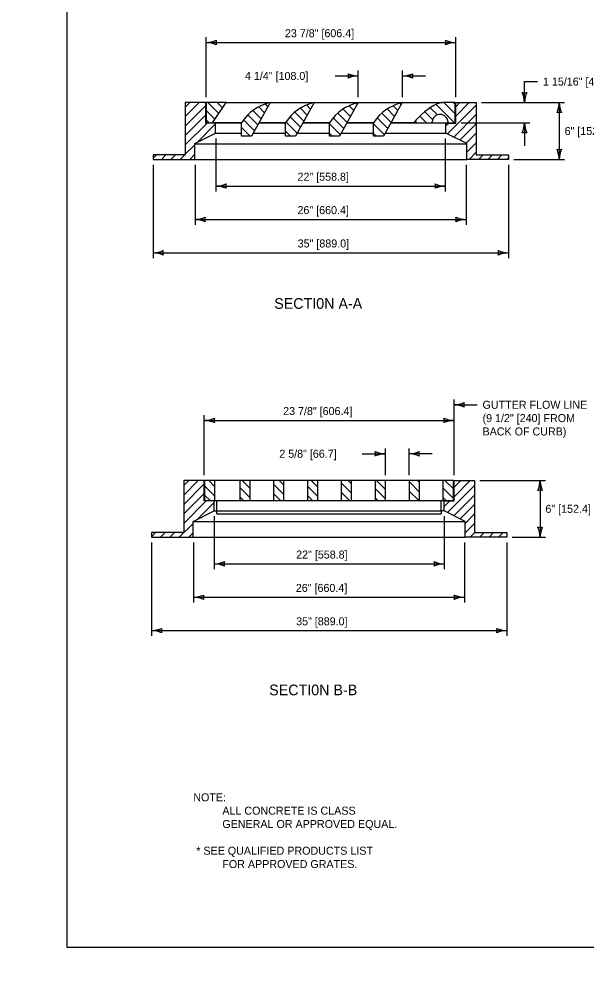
# Model space of a CAD drawing. Extents: x 49991.4 to 50021, y 49987.6 to 50011.4.
# Drawn here: x 49999.98 to 50004.23, y 49999.86 to 50007.02 of the extents above; entities that cross this region are included whole.
import ezdxf

# ---------------------------------------------------------------- set-up
doc = ezdxf.new("R2010")
doc.units = 0
for name, color, linetype in [('Level 1', 7, 'Continuous'), ('Level 2', 7, 'Continuous'), ('Level 3', 7, 'Continuous'), ('Level 4', 7, 'Continuous')]:
    doc.layers.add(name, color=color, linetype=linetype)

msp = doc.modelspace()

# ---------------------------------------------------------------- linework, layer by layer
at = {"layer": 'Level 1'}
for p, q in [((50001.3764, 50006.3907), (50001.2224, 50006.3907)), ((50001.2224, 50006.3907), (50001.2224, 50006)), ((50001.2224, 50006.3569), (50001.2562, 50006.3907)), ((50001.2224, 50006.2862), (50001.3269, 50006.3907)), ((50001.2224, 50006.2155), (50001.3764, 50006.3695)), ((50001.3764, 50006.237), (50001.3764, 50006.3907)), ((50001.5288, 50006.3907), (50001.3786, 50006.3907)), ((50001.3786, 50006.3907), (50001.3786, 50006.2393)), ((50001.4729, 50006.309), (50001.3912, 50006.3907)), ((50001.4251, 50006.2393), (50001.5288, 50006.3907)), ((50001.5016, 50006.351), (50001.4619, 50006.3907)), ((50001.5288, 50006.3907), (50003.1532, 50006.3907)), ((50001.8588, 50006.3907), (50001.7185, 50006.1398)), ((50001.8166, 50006.3153), (50001.7724, 50006.3596)), ((50001.842, 50006.3606), (50001.8222, 50006.3804)), ((50002.1888, 50006.3907), (50002.0485, 50006.1398)), ((50002.1618, 50006.3425), (50002.1314, 50006.3729)), ((50002.1872, 50006.3878), (50002.1852, 50006.3899)), ((50002.5188, 50006.3907), (50002.3785, 50006.1398)), ((50002.4859, 50006.3318), (50002.4499, 50006.3678)), ((50002.5112, 50006.3772), (50002.5018, 50006.3866)), ((50002.8488, 50006.3907), (50002.7085, 50006.1398)), ((50002.8159, 50006.3318), (50002.7799, 50006.3678)), ((50002.8412, 50006.3771), (50002.8317, 50006.3866)), ((50003.241, 50006.2393), (50003.1031, 50006.3772)), ((50003.2438, 50006.3907), (50003.1532, 50006.3907)), ((50003.2438, 50006.3072), (50003.1603, 50006.3907)), ((50003.1866, 50006.1565), (50003.4028, 50006.3727)), ((50003.2438, 50006.3779), (50003.231, 50006.3907)), ((50003.2438, 50006.2393), (50003.2438, 50006.3907)), ((50003.2438, 50006.2393), (50003.2438, 50006.3907)), ((50003.2488, 50006.237), (50003.2488, 50006.3907)), ((50003.2488, 50006.3907), (50003.4028, 50006.3907)), ((50003.2488, 50006.3602), (50003.2793, 50006.3907)), ((50003.2488, 50006.2894), (50003.3501, 50006.3907)), ((50003.4028, 50006.3907), (50003.4028, 50006)), ((50001.2224, 50006.1448), (50001.3764, 50006.2988)), ((50001.4441, 50006.2671), (50001.3786, 50006.3326)), ((50001.5003, 50006.3491), (50001.5003, 50006.3491)), ((50001.5003, 50006.3491), (50001.5003, 50006.3491)), ((50001.7659, 50006.2246), (50001.6912, 50006.2994)), ((50001.7913, 50006.2699), (50001.7292, 50006.332)), ((50002.1111, 50006.2518), (50002.0431, 50006.3198)), ((50002.1365, 50006.2971), (50002.0845, 50006.3491)), ((50002.4351, 50006.2411), (50002.3645, 50006.3117)), ((50002.4605, 50006.2864), (50002.404, 50006.343)), ((50002.7651, 50006.2411), (50002.6945, 50006.3117)), ((50002.7905, 50006.2864), (50002.734, 50006.343)), ((50003.0289, 50006.2393), (50002.9793, 50006.2888)), ((50003.0756, 50006.2632), (50003.0168, 50006.322)), ((50003.1116, 50006.298), (50003.058, 50006.3516)), ((50003.2337, 50006.133), (50003.4028, 50006.302)), ((50001.2224, 50006.0741), (50001.3853, 50006.237)), ((50001.3126, 50006.0936), (50001.4496, 50006.2306)), ((50001.4496, 50006.237), (50001.3764, 50006.237)), ((50001.4012, 50006.2393), (50001.3786, 50006.2619)), ((50001.3786, 50006.2393), (50001.4251, 50006.2393)), ((50001.644, 50006.2393), (50001.4251, 50006.2393)), ((50001.4428, 50006.2652), (50001.4428, 50006.2652)), ((50001.4428, 50006.2652), (50001.4428, 50006.2652)), ((50001.4496, 50006.162), (50001.4496, 50006.237)), ((50001.644, 50006.237), (50001.4496, 50006.237)), ((50001.644, 50006.1398), (50001.644, 50006.2393)), ((50001.7406, 50006.1792), (50001.6589, 50006.2609)), ((50001.974, 50006.237), (50001.7729, 50006.237)), ((50001.974, 50006.2393), (50001.7741, 50006.2393)), ((50001.974, 50006.1398), (50001.974, 50006.2393)), ((50002.0604, 50006.1611), (50001.9773, 50006.2441)), ((50002.0858, 50006.2064), (50002.0077, 50006.2845)), ((50002.304, 50006.237), (50002.1029, 50006.237)), ((50002.304, 50006.2393), (50002.1041, 50006.2393)), ((50002.304, 50006.1398), (50002.304, 50006.2393)), ((50002.3844, 50006.1504), (50002.304, 50006.2308)), ((50002.4098, 50006.1957), (50002.33, 50006.2755)), ((50002.634, 50006.237), (50002.4329, 50006.237)), ((50002.634, 50006.2393), (50002.4341, 50006.2393)), ((50002.634, 50006.1398), (50002.634, 50006.2393)), ((50002.7144, 50006.1504), (50002.634, 50006.2308)), ((50002.7398, 50006.1957), (50002.66, 50006.2755)), ((50003.1756, 50006.237), (50002.7629, 50006.237)), ((50002.9349, 50006.2393), (50002.7641, 50006.2393)), ((50002.9349, 50006.2393), (50003.0669, 50006.2393)), ((50002.9582, 50006.2393), (50002.9454, 50006.252)), ((50003.0669, 50006.2393), (50003.0672, 50006.2394)), ((50003.0669, 50006.2393), (50003.1966, 50006.2393)), ((50003.1756, 50006.162), (50003.1756, 50006.237)), ((50003.1756, 50006.237), (50003.2488, 50006.237)), ((50003.1756, 50006.2162), (50003.1964, 50006.237)), ((50003.1967, 50006.2393), (50003.2438, 50006.2393)), ((50003.2809, 50006.1094), (50003.4028, 50006.2313)), ((50001.2934, 50006.084), (50001.4496, 50006.162)), ((50001.4496, 50006.1607), (50001.644, 50006.1607)), ((50001.7093, 50006.1398), (50001.644, 50006.2051)), ((50001.7302, 50006.1607), (50001.974, 50006.1607)), ((50002.0109, 50006.1398), (50001.974, 50006.1767)), ((50002.0602, 50006.1607), (50002.304, 50006.1607)), ((50002.3243, 50006.1398), (50002.304, 50006.1601)), ((50002.3902, 50006.1607), (50002.634, 50006.1607)), ((50002.6543, 50006.1398), (50002.634, 50006.1601)), ((50002.7202, 50006.1607), (50003.1756, 50006.1607)), ((50003.3318, 50006.084), (50003.1756, 50006.162)), ((50003.3281, 50006.0859), (50003.4028, 50006.1606)), ((50001.2224, 50006.0034), (50001.2934, 50006.0744)), ((50001.2934, 50005.9654), (50001.2934, 50006.084)), ((50001.2934, 50006.0826), (50003.3318, 50006.0826)), ((50001.7185, 50006.1398), (50001.644, 50006.1398)), ((50002.0485, 50006.1398), (50001.974, 50006.1398)), ((50002.3785, 50006.1398), (50002.304, 50006.1398)), ((50002.7085, 50006.1398), (50002.634, 50006.1398)), ((50003.3318, 50006.0189), (50003.4028, 50006.0899)), ((50003.3318, 50005.9654), (50003.3318, 50006.084)), ((50001.2224, 50006), (50000.981, 50006)), ((50000.981, 50006), (50000.981, 50005.9654)), ((50000.981, 50005.9741), (50001.0069, 50006)), ((50001.043, 50005.9654), (50001.0776, 50006)), ((50001.1137, 50005.9654), (50001.1483, 50006)), ((50001.1844, 50005.9654), (50001.219, 50006)), ((50001.2551, 50005.9654), (50001.2934, 50006.0037)), ((50003.349, 50005.9654), (50003.4028, 50006.0192)), ((50003.4028, 50006), (50003.6442, 50006)), ((50003.4197, 50005.9654), (50003.4543, 50006)), ((50003.4904, 50005.9654), (50003.525, 50006)), ((50003.5612, 50005.9654), (50003.5958, 50006)), ((50003.6442, 50006), (50003.6442, 50005.9654)), ((50000.981, 50005.9654), (50001.2934, 50005.9654)), ((50001.2934, 50005.9654), (50003.3318, 50005.9654)), ((50003.6442, 50005.9654), (50003.3318, 50005.9654)), ((50003.6319, 50005.9654), (50003.6442, 50005.9777)), ((50001.3642, 50003.5597), (50001.2102, 50003.5597)), ((50001.2102, 50003.5597), (50001.2102, 50003.1691)), ((50001.2102, 50003.5207), (50001.2492, 50003.5597)), ((50001.2102, 50003.45), (50001.3199, 50003.5597)), ((50001.2102, 50003.3793), (50001.3642, 50003.5333)), ((50001.3642, 50003.406), (50001.3642, 50003.5597)), ((50001.3664, 50003.5597), (50001.3664, 50003.4083)), ((50001.3664, 50003.5597), (50001.3664, 50003.4083)), ((50003.2316, 50003.5597), (50001.3664, 50003.5597)), ((50001.3664, 50003.5597), (50001.3664, 50003.5594)), ((50001.3664, 50003.5597), (50001.3664, 50003.4083)), ((50001.4446, 50003.5597), (50001.3664, 50003.5597)), ((50001.4446, 50003.4422), (50001.3664, 50003.5204)), ((50001.4446, 50003.5129), (50001.3978, 50003.5597)), ((50001.4446, 50003.4083), (50001.4446, 50003.5597)), ((50001.63, 50003.5597), (50001.63, 50003.4083)), ((50001.7082, 50003.5597), (50001.63, 50003.5597)), ((50001.7082, 50003.4297), (50001.63, 50003.5079)), ((50001.7082, 50003.5004), (50001.6489, 50003.5597)), ((50001.7082, 50003.4083), (50001.7082, 50003.5597)), ((50001.8836, 50003.5597), (50001.8836, 50003.4083)), ((50001.9618, 50003.5597), (50001.8836, 50003.5597)), ((50001.9618, 50003.4534), (50001.8836, 50003.5316)), ((50001.9618, 50003.5241), (50001.9262, 50003.5597)), ((50001.9618, 50003.4083), (50001.9618, 50003.5597)), ((50002.1372, 50003.5597), (50002.1372, 50003.4083)), ((50002.2152, 50003.5597), (50002.1372, 50003.5597)), ((50002.2152, 50003.4386), (50002.1372, 50003.5166)), ((50002.2152, 50003.5093), (50002.1648, 50003.5597)), ((50002.2152, 50003.4083), (50002.2152, 50003.5597)), ((50002.3906, 50003.5597), (50002.3906, 50003.4083)), ((50002.4688, 50003.5597), (50002.3906, 50003.5597)), ((50002.4688, 50003.4635), (50002.3906, 50003.5417)), ((50002.4688, 50003.5342), (50002.4433, 50003.5597)), ((50002.4688, 50003.4083), (50002.4688, 50003.5597)), ((50002.6442, 50003.5597), (50002.6442, 50003.4083)), ((50002.7222, 50003.5597), (50002.6442, 50003.5597)), ((50002.7222, 50003.4214), (50002.6442, 50003.4994)), ((50002.7222, 50003.4921), (50002.6546, 50003.5597)), ((50002.7222, 50003.4083), (50002.7222, 50003.5597)), ((50002.8996, 50003.5597), (50002.8996, 50003.4083)), ((50002.9778, 50003.5597), (50002.8996, 50003.5597)), ((50002.9778, 50003.4728), (50002.8996, 50003.551)), ((50002.9778, 50003.5435), (50002.9616, 50003.5597)), ((50002.9778, 50003.4083), (50002.9778, 50003.5597)), ((50003.1536, 50003.5597), (50003.1536, 50003.4083)), ((50003.2316, 50003.5597), (50003.1536, 50003.5597)), ((50003.2316, 50003.4256), (50003.1536, 50003.5036)), ((50003.2316, 50003.4963), (50003.1682, 50003.5597)), ((50003.1881, 50003.3187), (50003.3906, 50003.5212)), ((50003.2316, 50003.4083), (50003.2316, 50003.5597)), ((50003.2366, 50003.406), (50003.2366, 50003.5597)), ((50003.2366, 50003.5597), (50003.3906, 50003.5597)), ((50003.2366, 50003.5087), (50003.2876, 50003.5597)), ((50003.2366, 50003.438), (50003.3583, 50003.5597)), ((50003.3906, 50003.5597), (50003.3906, 50003.1691)), ((50003.3906, 50003.5597), (50003.3906, 50003.1691)), ((50001.2102, 50003.3086), (50001.3642, 50003.4626)), ((50001.4078, 50003.4083), (50001.3664, 50003.4497)), ((50001.6589, 50003.4083), (50001.63, 50003.4372)), ((50001.9362, 50003.4083), (50001.8836, 50003.4609)), ((50002.1748, 50003.4083), (50002.1372, 50003.4459)), ((50002.4532, 50003.4083), (50002.3906, 50003.4709)), ((50002.6646, 50003.4083), (50002.6442, 50003.4287)), ((50002.9716, 50003.4083), (50002.8996, 50003.4803)), ((50003.1782, 50003.4083), (50003.1536, 50003.4329)), ((50003.2352, 50003.2952), (50003.3906, 50003.4505)), ((50001.2102, 50003.2379), (50001.3783, 50003.406)), ((50001.3109, 50003.2679), (50001.4374, 50003.3943)), ((50001.4374, 50003.406), (50001.3642, 50003.406)), ((50001.3664, 50003.4083), (50001.4446, 50003.4083)), ((50001.4374, 50003.3311), (50001.4374, 50003.406)), ((50001.4446, 50003.4083), (50001.4592, 50003.4083)), ((50001.4592, 50003.3091), (50001.4592, 50003.4083)), ((50001.63, 50003.4083), (50001.7082, 50003.4083)), ((50001.8836, 50003.4083), (50001.9618, 50003.4083)), ((50002.1372, 50003.4083), (50002.2152, 50003.4083)), ((50002.3906, 50003.4083), (50002.4688, 50003.4083)), ((50002.6442, 50003.4083), (50002.7222, 50003.4083)), ((50002.9009, 50003.4083), (50002.8996, 50003.4096)), ((50002.8996, 50003.4083), (50002.9778, 50003.4083)), ((50003.1388, 50003.3297), (50003.1388, 50003.4083)), ((50003.1388, 50003.4083), (50003.1536, 50003.4083)), ((50003.1536, 50003.4083), (50003.2316, 50003.4083)), ((50003.1634, 50003.3311), (50003.1634, 50003.406)), ((50003.1634, 50003.406), (50003.2366, 50003.406)), ((50003.1634, 50003.3648), (50003.2046, 50003.406)), ((50003.173, 50003.4083), (50003.2312, 50003.4083)), ((50003.2824, 50003.2716), (50003.3906, 50003.3798)), ((50001.2812, 50003.253), (50001.4374, 50003.3311)), ((50001.4374, 50003.3311), (50001.4592, 50003.3311)), ((50001.4592, 50003.3091), (50003.1388, 50003.3091)), ((50003.1634, 50003.3311), (50003.1388, 50003.3311)), ((50003.1388, 50003.3297), (50003.1388, 50003.3091)), ((50003.3196, 50003.253), (50003.1634, 50003.3311)), ((50003.3196, 50003.2381), (50003.3906, 50003.3091)), ((50001.1775, 50003.1344), (50001.2812, 50003.2381)), ((50001.2812, 50003.1344), (50001.2812, 50003.253)), ((50001.2812, 50003.2516), (50003.3196, 50003.2516)), ((50003.3196, 50003.1344), (50003.3196, 50003.253)), ((50003.3196, 50003.1674), (50003.3906, 50003.2384)), ((50001.2102, 50003.1691), (50000.9688, 50003.1691)), ((50000.9688, 50003.1691), (50000.9688, 50003.1344)), ((50000.9688, 50003.1379), (50001, 50003.1691)), ((50001.036, 50003.1344), (50001.0707, 50003.1691)), ((50001.1067, 50003.1344), (50001.1414, 50003.1691)), ((50001.2482, 50003.1344), (50001.2812, 50003.1674)), ((50003.3573, 50003.1344), (50003.392, 50003.1691)), ((50003.3906, 50003.1691), (50003.632, 50003.1691)), ((50003.428, 50003.1344), (50003.4627, 50003.1691)), ((50003.4987, 50003.1344), (50003.5334, 50003.1691)), ((50003.5694, 50003.1344), (50003.6041, 50003.1691)), ((50003.632, 50003.1691), (50003.632, 50003.1344)), ((50000.9688, 50003.1344), (50001.2812, 50003.1344)), ((50001.2834, 50003.1344), (50003.3196, 50003.1344)), ((50003.632, 50003.1344), (50003.3196, 50003.1344)), ((49999.9766, 49999.8624), (49999.9766, 49999.8624))]:
    msp.add_line(p, q, dxfattribs=at)
msp.add_lwpolyline([(50008.6146, 50011.2628), (50000.3356, 50011.2628), (50000.3356, 50000.0624), (50008.6146, 50000.0624)], close=True, dxfattribs=at)
for centre, radius, start, end in [((50001.9257, 50006.0677), 0.3298, 101.70095, 148.65461), ((50002.2557, 50006.0677), 0.3298, 101.70095, 148.65461), ((50002.5857, 50006.0677), 0.3298, 101.70095, 148.65461), ((50002.9157, 50006.0677), 0.3298, 101.70095, 148.65461), ((50003.3175, 50005.9452), 0.4825, 115.43955, 142.45364), ((50003.3175, 50005.9452), 0.4825, 115.43955, 142.45364), ((50003.1532, 50006.2907), 0.1, 90, 115.43595), ((50003.1532, 50006.2907), 0.1, 90, 115.43595), ((50003.1316, 50006.242), 0.06, 2.28125, 175.27663)]:
    msp.add_arc(centre, radius, start, end, dxfattribs=at)
for points in [[(50003.0672, 50006.2394), (50003.0681, 50006.2396), (50003.0691, 50006.2403), (50003.0702, 50006.2417), (50003.0709, 50006.2428), (50003.0715, 50006.2449), (50003.0718, 50006.2469)], [(50003.1915, 50006.2444), (50003.1916, 50006.2433), (50003.1916, 50006.2429), (50003.1917, 50006.2425), (50003.192, 50006.2416), (50003.1926, 50006.2407), (50003.1932, 50006.2404), (50003.1937, 50006.2401), (50003.1947, 50006.2397), (50003.196, 50006.2394), (50003.1967, 50006.2393)]]:
    msp.add_spline(points, degree=3, dxfattribs=at)
at = {"layer": 'Level 3'}
for p, q in [((50001.3786, 50006.4307), (50001.3786, 50006.8807)), ((50003.2488, 50006.4307), (50003.2488, 50006.8807)), ((50001.3786, 50006.8407), (50003.2488, 50006.8407)), ((50002.3454, 50006.5907), (50002.5188, 50006.5907)), ((50002.5188, 50006.4307), (50002.5188, 50006.6307)), ((50002.8502, 50006.4307), (50002.8502, 50006.6307)), ((50002.8502, 50006.5907), (50003.0236, 50006.5907)), ((50003.7644, 50006.3907), (50003.7644, 50006.5483)), ((50003.7644, 50006.5483), (50003.8629, 50006.5483)), ((50003.4428, 50006.3907), (50004.0651, 50006.3907)), ((50004.0251, 50006.3907), (50004.0251, 50005.9654)), ((50003.2888, 50006.2393), (50003.8044, 50006.2393)), ((50003.7644, 50006.2393), (50003.7644, 50006.0659)), ((50001.4518, 50006.1207), (50001.4518, 50005.7254)), ((50003.1706, 50006.1207), (50003.1706, 50005.7254)), ((50003.6842, 50005.9654), (50004.0651, 50005.9654)), ((50000.981, 50005.9254), (50000.981, 50005.2254)), ((50001.2956, 50005.9254), (50001.2956, 50005.4754)), ((50003.3268, 50005.9254), (50003.3268, 50005.4754)), ((50003.6442, 50005.9254), (50003.6442, 50005.2254)), ((50001.4518, 50005.7654), (50003.1706, 50005.7654)), ((50001.2956, 50005.5154), (50003.3268, 50005.5154)), ((50000.981, 50005.2654), (50003.6442, 50005.2654)), ((50003.2366, 50003.5997), (50003.2366, 50004.1668)), ((50003.2366, 50004.1268), (50003.41, 50004.1268)), ((50001.3642, 50003.5997), (50001.3642, 50004.0497)), ((50001.3642, 50004.0097), (50003.2366, 50004.0097)), ((50002.7222, 50003.5997), (50002.7222, 50003.7997)), ((50002.8996, 50003.5997), (50002.8996, 50003.7997)), ((50002.5488, 50003.7597), (50002.7222, 50003.7597)), ((50003.073, 50003.7597), (50002.8996, 50003.7597)), ((50003.4306, 50003.5597), (50003.9212, 50003.5597)), ((50003.8812, 50003.5597), (50003.8812, 50003.1344)), ((50001.4389, 50003.2911), (50001.4389, 50002.8944)), ((50003.1634, 50003.2911), (50003.1634, 50002.8944)), ((50000.9688, 50003.0944), (50000.9688, 50002.3944)), ((50001.2834, 50003.0944), (50001.2834, 50002.6444)), ((50003.3146, 50003.0944), (50003.3146, 50002.6444)), ((50003.632, 50003.0944), (50003.632, 50002.3944)), ((50003.672, 50003.1344), (50003.9212, 50003.1344)), ((50001.4389, 50002.9344), (50003.1634, 50002.9344)), ((50001.2834, 50002.6844), (50003.3146, 50002.6844)), ((50000.9688, 50002.4344), (50003.632, 50002.4344))]:
    msp.add_line(p, q, dxfattribs=at)
for centre, radius, start, end in [((50001.3671, 50007.0734), 0.233, 272.82731, 292.07716), ((50001.5068, 50006.8407), 0.0548, 162.13882, 197.86118), ((50003.258, 50007.0628), 0.2223, 247.45601, 267.63952), ((50003.1206, 50006.8407), 0.0548, 342.13882, 17.86118), ((50001.3694, 50006.6186), 0.2223, 67.45601, 87.63952), ((50003.2603, 50006.608), 0.233, 92.82731, 112.07716), ((50002.528, 50006.8128), 0.2223, 247.45601, 267.63952), ((50002.3906, 50006.5907), 0.0548, 342.13882, 17.86118), ((50002.5303, 50006.358), 0.233, 92.82731, 112.07716), ((50002.8387, 50006.8234), 0.233, 272.82731, 292.07716), ((50002.841, 50006.3686), 0.2223, 67.45601, 87.63952), ((50002.9784, 50006.5907), 0.0548, 162.13882, 197.86118), ((50003.7644, 50006.5189), 0.0548, 252.13882, 287.86118), ((50003.5317, 50006.3792), 0.233, 2.82731, 22.07716), ((50003.9865, 50006.3815), 0.2223, 157.45601, 177.63952), ((50003.803, 50006.3999), 0.2223, 337.45601, 357.63952), ((50004.2578, 50006.4022), 0.233, 182.82731, 202.07716), ((50004.0251, 50006.2625), 0.0548, 72.13882, 107.86118), ((50003.5423, 50006.2485), 0.2223, 337.45601, 357.63952), ((50003.9971, 50006.2508), 0.233, 182.82731, 202.07716), ((50003.7644, 50006.1111), 0.0548, 72.13882, 107.86118), ((50004.0251, 50006.0936), 0.0548, 252.13882, 287.86118), ((50003.7924, 50005.9539), 0.233, 2.82731, 22.07716), ((50004.0251, 50006.0936), 0.0548, 252.13882, 287.86118), ((50003.7924, 50005.9539), 0.233, 2.82731, 22.07716), ((50004.2472, 50005.9562), 0.2223, 157.45601, 177.63952), ((50004.2472, 50005.9562), 0.2223, 157.45601, 177.63952), ((50001.4403, 50005.9981), 0.233, 272.82731, 292.07716), ((50001.4426, 50005.5433), 0.2223, 67.45601, 87.63952), ((50001.58, 50005.7654), 0.0548, 162.13882, 197.86118), ((50003.1798, 50005.9875), 0.2223, 247.45601, 267.63952), ((50003.0424, 50005.7654), 0.0548, 342.13882, 17.86118), ((50003.1821, 50005.5327), 0.233, 92.82731, 112.07716), ((50001.2841, 50005.7481), 0.233, 272.82731, 292.07716), ((50001.2841, 50005.7481), 0.233, 272.82731, 292.07716), ((50001.2864, 50005.2933), 0.2223, 67.45601, 87.63952), ((50001.2864, 50005.2933), 0.2223, 67.45601, 87.63952), ((50001.4238, 50005.5154), 0.0548, 162.13882, 197.86118), ((50001.4238, 50005.5154), 0.0548, 162.13882, 197.86118), ((50003.336, 50005.7375), 0.2223, 247.45601, 267.63952), ((50003.1986, 50005.5154), 0.0548, 342.13882, 17.86118), ((50003.336, 50005.7375), 0.2223, 247.45601, 267.63952), ((50003.1986, 50005.5154), 0.0548, 342.13882, 17.86118), ((50003.3383, 50005.2827), 0.233, 92.82731, 112.07716), ((50003.3383, 50005.2827), 0.233, 92.82731, 112.07716), ((50000.9695, 50005.4981), 0.233, 272.82731, 292.07716), ((50000.9718, 50005.0433), 0.2223, 67.45601, 87.63952), ((50001.1092, 50005.2654), 0.0548, 162.13882, 197.86118), ((50003.6534, 50005.4875), 0.2223, 247.45601, 267.63952), ((50003.516, 50005.2654), 0.0548, 342.13882, 17.86118), ((50003.6557, 50005.0327), 0.233, 92.82731, 112.07716), ((50003.2251, 50004.3595), 0.233, 272.82731, 292.07716), ((50003.3648, 50004.1268), 0.0548, 162.13882, 197.86118), ((50003.2274, 50003.9047), 0.2223, 67.45601, 87.63952), ((50001.3527, 50004.2424), 0.233, 272.82731, 292.07716), ((50001.355, 50003.7876), 0.2223, 67.45601, 87.63952), ((50001.4924, 50004.0097), 0.0548, 162.13882, 197.86118), ((50003.2458, 50004.2318), 0.2223, 247.45601, 267.63952), ((50003.1084, 50004.0097), 0.0548, 342.13882, 17.86118), ((50003.2481, 50003.777), 0.233, 92.82731, 112.07716), ((50002.7314, 50003.9818), 0.2223, 247.45601, 267.63952), ((50002.594, 50003.7597), 0.0548, 342.13882, 17.86118), ((50002.7337, 50003.527), 0.233, 92.82731, 112.07716), ((50002.8881, 50003.9924), 0.233, 272.82731, 292.07716), ((50002.8904, 50003.5376), 0.2223, 67.45601, 87.63952), ((50003.0278, 50003.7597), 0.0548, 162.13882, 197.86118), ((50003.6591, 50003.5689), 0.2223, 337.45601, 357.63952), ((50004.1139, 50003.5712), 0.233, 182.82731, 202.07716), ((50003.8812, 50003.4315), 0.0548, 72.13882, 107.86118), ((50003.8812, 50003.2626), 0.0548, 252.13882, 287.86118), ((50003.6485, 50003.1229), 0.233, 2.82731, 22.07716), ((50004.1033, 50003.1252), 0.2223, 157.45601, 177.63952), ((50001.4274, 50003.1671), 0.233, 272.82731, 292.07716), ((50001.4297, 50002.7123), 0.2223, 67.45601, 87.63952), ((50001.5671, 50002.9344), 0.0548, 162.13882, 197.86118), ((50003.1726, 50003.1565), 0.2223, 247.45601, 267.63952), ((50003.0352, 50002.9344), 0.0548, 342.13882, 17.86118), ((50003.1749, 50002.7017), 0.233, 92.82731, 112.07716), ((50001.2719, 50002.9171), 0.233, 272.82731, 292.07716), ((50001.2742, 50002.4623), 0.2223, 67.45601, 87.63952), ((50001.4116, 50002.6844), 0.0548, 162.13882, 197.86118), ((50003.3238, 50002.9065), 0.2223, 247.45601, 267.63952), ((50003.1864, 50002.6844), 0.0548, 342.13882, 17.86118), ((50003.3261, 50002.4517), 0.233, 92.82731, 112.07716), ((50000.9573, 50002.6671), 0.233, 272.82731, 292.07716), ((50000.9596, 50002.2123), 0.2223, 67.45601, 87.63952), ((50001.097, 50002.4344), 0.0548, 162.13882, 197.86118), ((50003.6412, 50002.6565), 0.2223, 247.45601, 267.63952), ((50003.5038, 50002.4344), 0.0548, 342.13882, 17.86118), ((50003.6435, 50002.2017), 0.233, 92.82731, 112.07716)]:
    msp.add_arc(centre, radius, start, end, dxfattribs=at)
at = {"layer": 'Level 4'}
for p, q in [((50001.4592, 50003.4083), (50003.1388, 50003.4083)), ((50001.4592, 50003.3311), (50003.1388, 50003.3311))]:
    msp.add_line(p, q, dxfattribs=at)

# ---------------------------------------------------------------- texts
at = {"layer": 'Level 2'}
for s, height, p in [('23 7/8" [606.4]', 0.06, (50001.9688, 50006.8807)), ('4 1/4" [108.0]', 0.06, (50001.6695, 50006.5607)), ('1 15/16" [49.2]', 0.06, (50003.9029, 50006.5183)), ('6" [152.4]', 0.06, (50004.0651, 50006.148)), ('22" [558.8]', 0.06, (50002.0631, 50005.8054)), ('26" [660.4]', 0.06, (50002.0631, 50005.5554)), ('35" [889.0]', 0.06, (50002.0645, 50005.3054)), ('SECTI0N A-A', 0.08, (50001.8885, 50004.8456)), ('GUTTER FLOW LINE', 0.06, (50003.45, 50004.0968)), ('23 7/8" [606.4]', 0.06, (50001.9555, 50004.0497)), ('(9 1/2" [240] FROM', 0.06, (50003.45, 50003.9968)), ('BACK OF CURB)', 0.06, (50003.45, 50003.8968)), ('2 5/8" [66.7]', 0.06, (50001.9267, 50003.7297)), ('6" [152.4]', 0.06, (50003.9212, 50003.3171)), ('22" [558.8]', 0.06, (50002.0531, 50002.9744)), ('26" [660.4]', 0.06, (50002.0509, 50002.7244)), ('35" [889.0]', 0.06, (50002.0529, 50002.4744)), ('SECTI0N B-B', 0.08, (50001.851, 50001.9501)), (' NOTE:', 0.06, (50001.26, 50001.1555)), ('ALL CONCRETE IS CLASS', 0.06, (50001.5, 50001.0555)), ('GENERAL OR APPROVED EQUAL.', 0.06, (50001.5, 50000.9555)), ('  * SEE QUALIFIED PRODUCTS LIST ', 0.06, (50001.26, 50000.7555)), ('FOR APPROVED GRATES.', 0.06, (50001.5, 50000.6555))]:
    msp.add_text(s, height=height, dxfattribs=at).set_placement(p)

doc.saveas('drawing.dxf')
